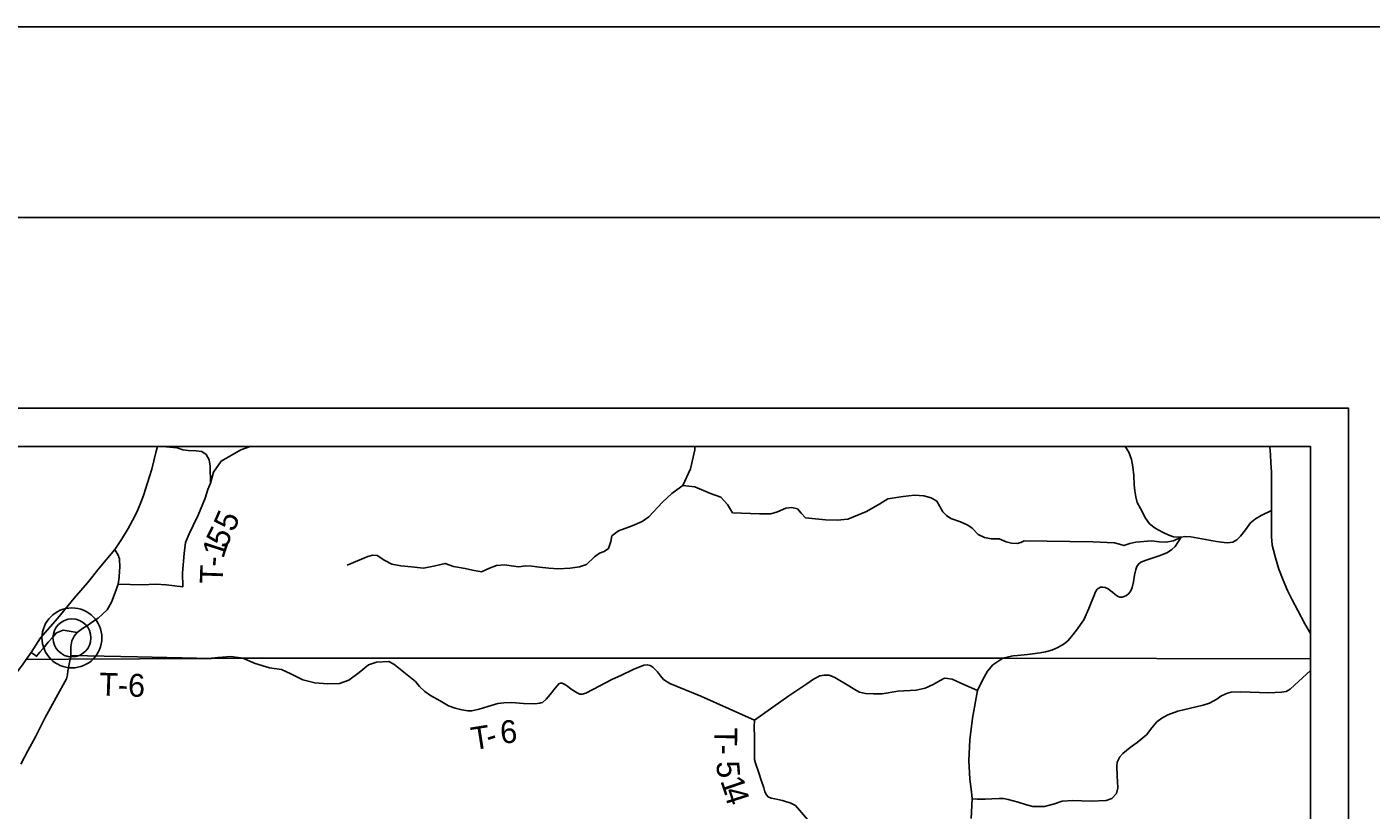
# Model space of a CAD drawing. Extents: x 0 to 2329303, y 0 to 694397.
# Drawn here: x 5.532 to 9.059, y 19.946 to 22 of the extents above; entities that cross this region are included whole.
import ezdxf

# ---------------------------------------------------------------- set-up
doc = ezdxf.new("R2010")
doc.units = 0
for name, color, linetype in [('GM_X_County_Road', 7, 'Continuous'), ('GM_X_State_Route', 7, 'Continuous'), ('GM_X_Township', 7, 'Continuous'), ('GM_X_Township_Road', 7, 'Continuous'), ('GM_X_Township_Road_Text', 7, 'Continuous'), ('GM_X_Township_ROW', 7, 'Continuous'), ('GM_X_Unincorporated', 7, 'Continuous'), ('SH_Border', 7, 'Continuous'), ('SH_Cut_Line', 7, 'Continuous'), ('SH_Data', 7, 'Continuous')]:
    doc.layers.add(name, color=color, linetype=linetype)

msp = doc.modelspace()

# ---------------------------------------------------------------- linework, layer by layer
at = {"layer": 'GM_X_County_Road'}
for points in [[(8.674, 20.648), (8.6821, 20.6471), (8.6962, 20.6488), (8.7067, 20.6548), (8.7165, 20.6641), (8.73, 20.6813), (8.7433, 20.6991), (8.7561, 20.71), (8.7707, 20.719), (8.7978, 20.7321)], [(8.1318, 20.3517), (8.158, 20.3541), (8.1914, 20.3586), (8.2054, 20.3611), (8.2214, 20.3658), (8.2373, 20.3729), (8.2542, 20.3824), (8.264, 20.3903), (8.2731, 20.4011), (8.2863, 20.418), (8.3054, 20.4455), (8.3189, 20.4747), (8.3277, 20.4964), (8.3318, 20.5074), (8.3361, 20.5189), (8.3406, 20.5252), (8.3446, 20.5284), (8.3495, 20.5306), (8.3556, 20.531), (8.3613, 20.5302), (8.3692, 20.5261), (8.3751, 20.5221), (8.3805, 20.5174), (8.3865, 20.5123), (8.3909, 20.509), (8.3954, 20.5063), (8.4001, 20.5049), (8.4064, 20.5049), (8.4115, 20.5065), (8.4177, 20.5089), (8.4237, 20.514), (8.429, 20.5209), (8.4325, 20.5296), (8.4359, 20.5447), (8.4389, 20.5625), (8.4416, 20.5769), (8.4444, 20.585), (8.4489, 20.5912), (8.4553, 20.5962), (8.4691, 20.6017), (8.5058, 20.6136), (8.5251, 20.6219), (8.5362, 20.6293), (8.5448, 20.6374), (8.5609, 20.6618), (8.5703, 20.6636), (8.5859, 20.6628), (8.6249, 20.656), (8.6538, 20.6507), (8.6666, 20.6489), (8.674, 20.648)], [(8.0099, 19.9239), (8.0125, 19.9753), (8.0106, 19.9938), (8.0061, 20.0273), (8.0035, 20.0762), (8.0062, 20.1307), (8.0134, 20.1871), (8.0263, 20.2594), (8.0398, 20.2871), (8.0525, 20.3104), (8.0672, 20.3273), (8.0934, 20.3443), (8.1158, 20.3499), (8.12, 20.3506), (8.1318, 20.3517)]]:
    msp.add_lwpolyline(points, dxfattribs=at)
at = {"layer": 'GM_X_State_Route'}
for points in [[(5.7803, 20.6561), (5.7978, 20.6843), (5.8098, 20.7052), (5.8215, 20.7289), (5.8332, 20.7568), (5.8393, 20.7737), (5.8481, 20.8018), (5.86, 20.8406), (5.8709, 20.8843), (5.8751, 20.9)], [(8.9, 20.4093), (8.8857, 20.4349), (8.8667, 20.4699), (8.8522, 20.4972), (8.8397, 20.5216), (8.8285, 20.5492), (8.8176, 20.5776), (8.8081, 20.6075), (8.8029, 20.6276), (8.7996, 20.6413), (8.7979, 20.6632), (8.7982, 20.6845), (8.7982, 20.7141), (8.7978, 20.7321), (8.798, 20.7498), (8.7979, 20.7704), (8.7977, 20.8052), (8.7977, 20.8328), (8.7966, 20.8572), (8.7956, 20.8782), (8.7937, 20.8992), (8.7936, 20.9)], [(5.5164, 20.0666), (5.5349, 20.1016), (5.555, 20.1381), (5.5795, 20.1869), (5.6092, 20.2411), (5.6362, 20.2908), (5.6391, 20.3005), (5.64, 20.3117), (5.6458, 20.3417), (5.6478, 20.3514), (5.6478, 20.3741), (5.6507, 20.3897), (5.6561, 20.4021), (5.6643, 20.4118), (5.678, 20.4222), (5.6914, 20.4306), (5.7075, 20.442), (5.7197, 20.4498), (5.7311, 20.4599), (5.7427, 20.471), (5.7549, 20.4914), (5.764, 20.517), (5.7716, 20.5386), (5.7745, 20.557), (5.7757, 20.5737), (5.7761, 20.5831), (5.7761, 20.5896), (5.7759, 20.598), (5.7751, 20.605), (5.7738, 20.6096), (5.7725, 20.6131), (5.7635, 20.6292), (5.7737, 20.6454), (5.7803, 20.6561)], [(5.5019, 20.3015), (5.5211, 20.327), (5.5308, 20.3409), (5.5439, 20.3593), (5.5686, 20.3975), (5.6124, 20.4489), (5.6569, 20.5022), (5.6914, 20.5425), (5.7219, 20.5802), (5.7635, 20.6292)]]:
    msp.add_lwpolyline(points, dxfattribs=at)
at = {"layer": 'GM_X_Township'}
msp.add_lwpolyline([(5.5308, 20.3409), (5.6417, 20.3416), (6.0156, 20.3441), (6.099, 20.3446), (8.0934, 20.3443), (8.9, 20.3432)], dxfattribs=at)
at = {"layer": 'GM_X_Township_Road'}
for points in [[(5.8842, 20.9), (5.8877, 20.8996), (5.9073, 20.8975), (5.9272, 20.8959), (5.9416, 20.8913), (5.956, 20.8888), (5.9763, 20.8887), (5.9914, 20.8866), (6.0027, 20.8788), (6.0109, 20.8646), (6.0136, 20.8479), (6.0139, 20.8038)], [(6.0139, 20.8038), (6.0224, 20.8322), (6.0419, 20.8613), (6.094, 20.8909), (6.1179, 20.9)], [(8.5609, 20.6618), (8.5406, 20.6627), (8.5285, 20.6672), (8.5123, 20.6753), (8.4927, 20.6857), (8.4783, 20.6971), (8.4677, 20.7121), (8.4543, 20.7373), (8.4459, 20.7529), (8.4416, 20.7676), (8.4391, 20.7833), (8.4373, 20.7995), (8.4368, 20.8233), (8.434, 20.8463), (8.4305, 20.8655), (8.4236, 20.8844), (8.4143, 20.8993), (8.4137, 20.9)], [(5.9417, 20.5315), (5.941, 20.5681), (5.945, 20.6187), (5.9489, 20.6482), (5.958, 20.6707), (5.9688, 20.6924), (5.9819, 20.7193), (6.0006, 20.7645), (6.007, 20.7865), (6.0139, 20.8038)], [(8.399, 20.6432), (8.4102, 20.6398), (8.4264, 20.6456), (8.4423, 20.6489), (8.4835, 20.6522), (8.5035, 20.6498), (8.5205, 20.6484), (8.5407, 20.6519), (8.5609, 20.6618)], [(5.7716, 20.5386), (5.8353, 20.5373), (5.8711, 20.5383), (5.8978, 20.5371), (5.9417, 20.5315)], [(5.5998, 20.3991), (5.6102, 20.4106), (5.6281, 20.4178), (5.6643, 20.4118)], [(5.6478, 20.3514), (5.8227, 20.348)], [(6.8808, 20.2272), (6.8851, 20.2285), (6.8945, 20.2369), (6.9054, 20.2493), (6.9186, 20.266), (6.9235, 20.2724), (6.9279, 20.2774), (6.9328, 20.2793), (6.9369, 20.279), (6.9423, 20.2763), (6.9505, 20.2709), (6.9603, 20.2633), (6.976, 20.2534), (6.983, 20.2502), (6.9891, 20.2506), (6.9987, 20.2526), (7.0176, 20.2621), (7.0693, 20.2898), (7.0906, 20.2993), (7.1235, 20.3148), (7.1515, 20.3261), (7.1601, 20.3274), (7.1675, 20.3257), (7.1747, 20.3208), (7.1866, 20.309), (7.1947, 20.2982), (7.2027, 20.2887), (7.2191, 20.2783), (7.3005, 20.2446), (7.3753, 20.2118), (7.4413, 20.1824), (7.5315, 20.2459), (7.5788, 20.2772), (7.5966, 20.2895), (7.6132, 20.2981), (7.6251, 20.3001), (7.6376, 20.3003), (7.6519, 20.2942), (7.6889, 20.2717), (7.7028, 20.263), (7.7169, 20.2556), (7.733, 20.2516), (7.7541, 20.2507), (7.7764, 20.2513), (7.8172, 20.2578), (7.8655, 20.2609), (7.889, 20.2656), (7.9104, 20.2757), (7.9283, 20.2864), (7.9404, 20.292), (7.9482, 20.2916), (7.9602, 20.2891), (7.983, 20.2789), (8.0263, 20.2594)], [(8.0125, 19.9753), (8.0255, 19.9747), (8.0467, 19.9747), (8.0645, 19.9757), (8.0837, 19.9769), (8.0945, 19.9767), (8.1072, 19.9743), (8.1332, 19.9671), (8.1555, 19.9603), (8.172, 19.9556), (8.1895, 19.9552), (8.2027, 19.9558), (8.2282, 19.9622), (8.2488, 19.9694), (8.2757, 19.9711), (8.3252, 19.97), (8.364, 19.9713), (8.3793, 19.9766), (8.3917, 19.9898), (8.3946, 20.0043), (8.3928, 20.0361), (8.3921, 20.0611), (8.3932, 20.0715), (8.3996, 20.0858), (8.4083, 20.0944), (8.4268, 20.1105), (8.4457, 20.1236), (8.4696, 20.1439), (8.4836, 20.1621), (8.4968, 20.1776), (8.5103, 20.1871), (8.5259, 20.1961), (8.5523, 20.2055), (8.6189, 20.2211), (8.6357, 20.2263), (8.6546, 20.2369), (8.6653, 20.2448), (8.68, 20.2518), (8.6921, 20.255), (8.7173, 20.2561), (8.791, 20.2538), (8.8246, 20.2552), (8.8364, 20.257), (8.8467, 20.263), (8.8586, 20.2739), (8.9, 20.3124)], [(6.6986, 20.2068), (6.6997, 20.2068), (6.7189, 20.2106), (6.7416, 20.2179), (6.7679, 20.2254), (6.7836, 20.2277), (6.8052, 20.2284), (6.8354, 20.2261), (6.8651, 20.225), (6.8779, 20.2263), (6.8808, 20.2272)], [(7.4413, 20.1824), (7.4406, 20.1643), (7.4416, 20.1374), (7.4419, 20.1046), (7.4413, 20.0785), (7.4439, 20.0689), (7.4532, 20.0435), (7.4594, 20.0243), (7.4657, 20.0042), (7.4689, 19.9942), (7.4727, 19.9862), (7.4771, 19.9806), (7.4849, 19.9778), (7.4946, 19.9758), (7.5028, 19.9739)]]:
    msp.add_lwpolyline(points, dxfattribs=at)
at = {"layer": 'GM_X_Township_ROW'}
for points in [[(7.2535, 20.797), (7.274, 20.8409), (7.2852, 20.8913), (7.2849, 20.9)], [(6.373, 20.5886), (6.4274, 20.6116), (6.4405, 20.6148), (6.4513, 20.614), (6.4717, 20.6006), (6.4896, 20.5912), (6.5138, 20.5868), (6.5414, 20.5841), (6.5727, 20.5807), (6.6033, 20.5869), (6.6299, 20.593), (6.6521, 20.5853), (6.6827, 20.5795), (6.7012, 20.5757), (6.7249, 20.5713), (6.7462, 20.5804), (6.7648, 20.5878), (6.7863, 20.5889), (6.8035, 20.5871), (6.8232, 20.5845), (6.8403, 20.5863), (6.8571, 20.586), (6.8772, 20.5831), (6.9021, 20.5803), (6.9269, 20.5791), (6.9576, 20.5805), (6.9823, 20.5841), (7.0005, 20.5904), (7.0214, 20.6107), (7.0347, 20.6195), (7.0474, 20.6239), (7.0583, 20.6323), (7.0645, 20.6501), (7.0672, 20.6651), (7.0843, 20.6784), (7.1207, 20.6916), (7.1471, 20.7029), (7.1643, 20.7151), (7.2005, 20.754), (7.225, 20.7768), (7.2375, 20.786), (7.2535, 20.797), (7.2852, 20.7936), (7.3257, 20.7765), (7.3536, 20.7666), (7.3706, 20.7476), (7.3841, 20.726), (7.4542, 20.7231), (7.4842, 20.7229), (7.502, 20.7279), (7.5236, 20.7382), (7.5392, 20.7395), (7.5541, 20.7364), (7.564, 20.7247), (7.5757, 20.7123), (7.6274, 20.7072), (7.6586, 20.7062), (7.6861, 20.7095), (7.7358, 20.7292), (7.7703, 20.7496), (7.7914, 20.7623), (7.832, 20.7688), (7.8615, 20.7718), (7.8859, 20.7702), (7.9049, 20.7648), (7.9195, 20.7561), (7.936, 20.7286), (7.9456, 20.7189), (7.9562, 20.7109), (7.9817, 20.7025), (8.0016, 20.6935), (8.0122, 20.6851), (8.0283, 20.6692), (8.045, 20.6613), (8.0627, 20.6571), (8.0835, 20.6578), (8.1017, 20.65), (8.1162, 20.6465), (8.1303, 20.6449), (8.1402, 20.6477), (8.1488, 20.6524), (8.3296, 20.6496), (8.3864, 20.647), (8.399, 20.6432)], [(5.5667, 20.3602), (5.5751, 20.37), (5.5882, 20.3861), (5.5998, 20.3991)], [(5.5439, 20.3593), (5.5578, 20.3498), (5.5667, 20.3602)], [(5.8227, 20.348), (6.0156, 20.3441), (6.0181, 20.3444)], [(6.0181, 20.3444), (6.0345, 20.3465), (6.0676, 20.3486), (6.099, 20.3446), (6.1316, 20.3307), (6.1689, 20.3193), (6.2003, 20.3149), (6.2252, 20.3034), (6.2562, 20.2878), (6.2878, 20.2798), (6.3219, 20.2771), (6.3531, 20.2783), (6.3772, 20.2873), (6.404, 20.3072), (6.4285, 20.327), (6.4496, 20.3337), (6.4824, 20.3361), (6.4955, 20.3292), (6.5522, 20.2832), (6.5627, 20.27), (6.5765, 20.257), (6.5914, 20.2471), (6.617, 20.2324), (6.6388, 20.2196), (6.6563, 20.2133), (6.6736, 20.2095), (6.6893, 20.2065), (6.6986, 20.2068)], [(7.5028, 19.9739), (7.5153, 19.9712), (7.5255, 19.9681), (7.5352, 19.9654), (7.5487, 19.9583), (7.7701, 19.7002)]]:
    msp.add_lwpolyline(points, dxfattribs=at)
at = {"layer": 'GM_X_Unincorporated'}
for radius in [0.0786, 0.0498]:
    msp.add_circle((5.6507, 20.3978), radius, dxfattribs=at)
at = {"layer": 'SH_Border'}
msp.add_lwpolyline([(1.5, 21.5), (33.5, 21.5), (33.5, 0.5), (1.5, 0.5)], close=True, dxfattribs=at)
at = {"layer": 'SH_Cut_Line'}
msp.add_lwpolyline([(0, 0), (34, 0), (34, 22), (0, 22)], close=True, dxfattribs=at)
at = {"layer": 'SH_Data'}
for points in [[(2, 21), (9, 21), (9, 14), (2, 14)], [(2.1, 20.9), (8.9, 20.9), (8.9, 14.1), (2.1, 14.1)]]:
    msp.add_lwpolyline(points, close=True, dxfattribs=at)

# ---------------------------------------------------------------- texts
at = {"layer": 'GM_X_Township_Road_Text'}
for s, rotation, p in [('5', 66.2308, (6.0749, 20.6732)), ('5', 63.4698, (6.0538, 20.6297)), ('1', 72.0012, (6.0477, 20.6038)), ('-', 84.7625, (6.0465, 20.5827)), ('T', 87.9896, (6.0458, 20.5387)), ('T-6', 358.0919, (5.7213, 20.2467)), ('6', 4.6573, (6.7764, 20.1201)), ('T', 8.9762, (6.703, 20.1031)), ('-', 17.2386, (6.7456, 20.1101)), ('T', 269.4472, (7.3364, 20.1633)), ('-', 269.8376, (7.3368, 20.118)), ('5', 274.5439, (7.3412, 20.0727)), ('1', 288.909, (7.3512, 20.0233)), ('4', 287.8228, (7.3593, 19.9967))]:
    msp.add_text(s, height=0.06, rotation=rotation, dxfattribs=at).set_placement(p)

doc.saveas('drawing.dxf')
